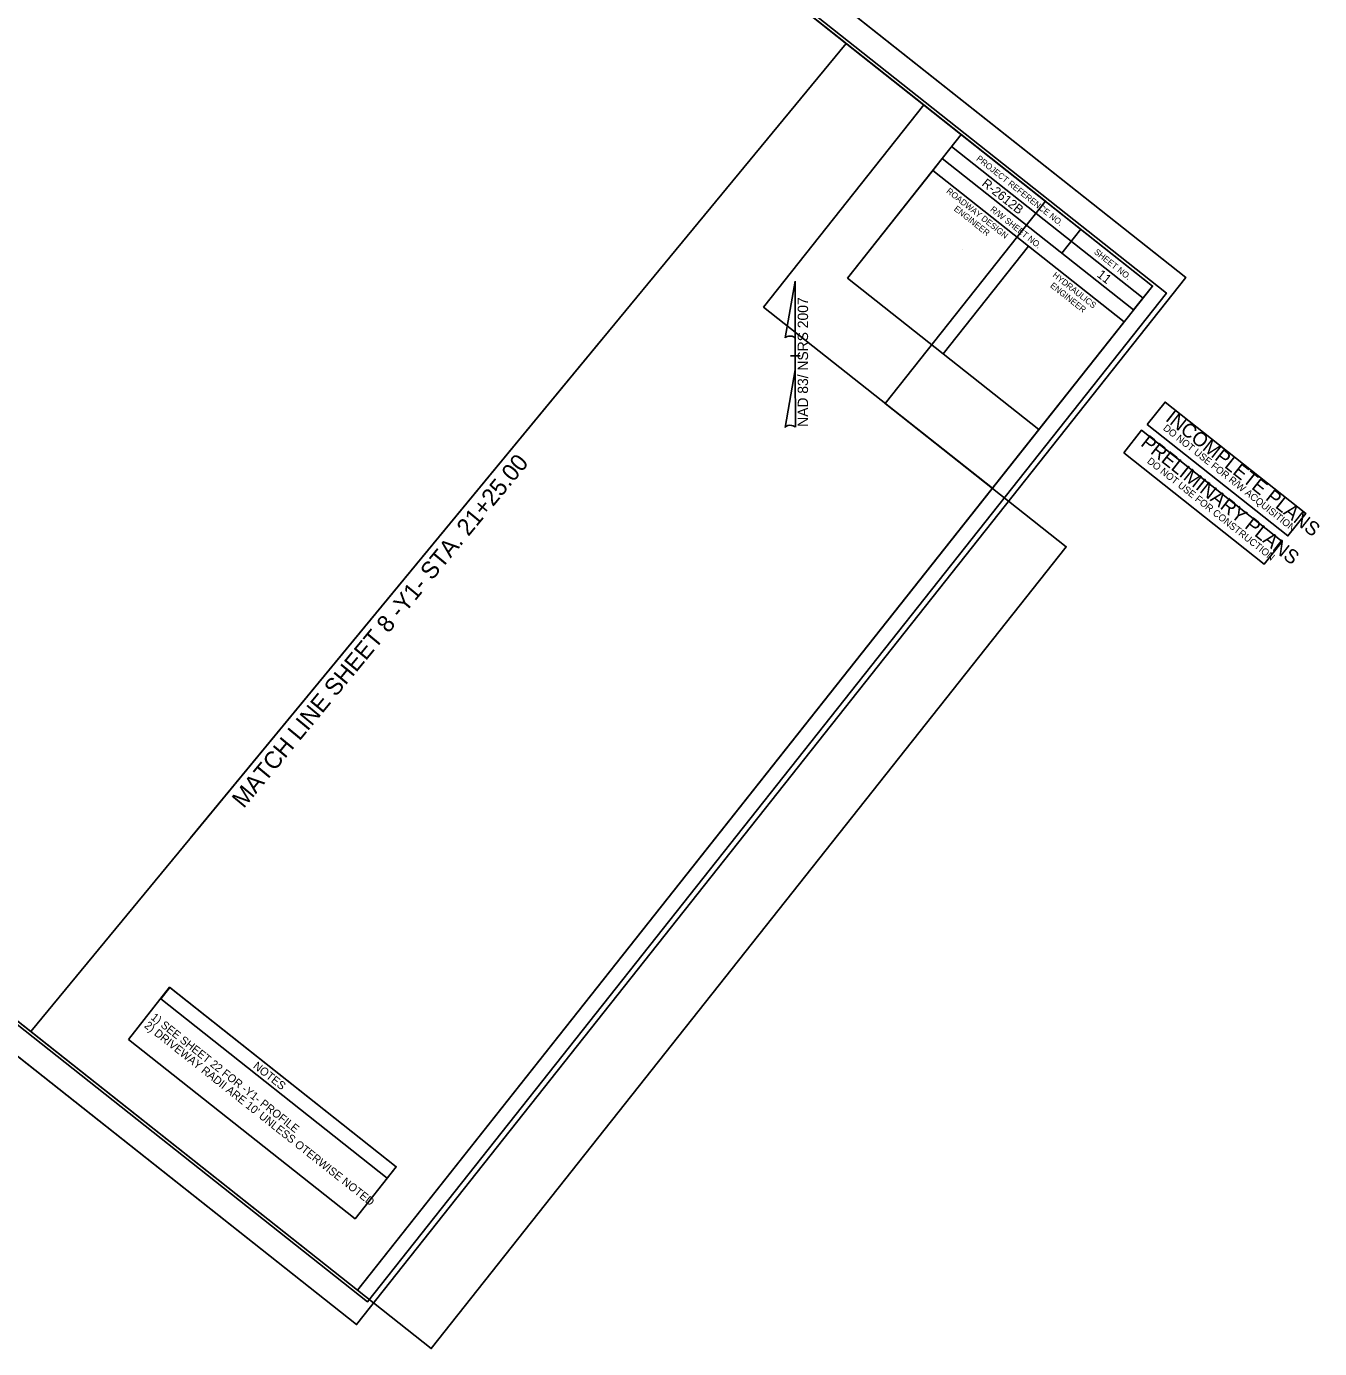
# Model space of a CAD drawing. Extents: x 1781036 to 1783156, y 813899 to 815868.
# Drawn here: x 1782096 to 1783156, y 813899 to 814983 of the extents above; entities that cross this region are included whole.
import ezdxf

# ---------------------------------------------------------------- set-up
doc = ezdxf.new("R2010")
doc.units = 0
for name, color, linetype in [('Matchline', 7, 'Continuous'), ('Matchline Text', 7, 'Continuous'), ('Prop DSN Text', 7, 'Continuous'), ('Prop Grid Mask', 7, 'Continuous'), ('Prop North Arrow NAD83 for Plan Sheets CELL', 7, 'Continuous'), ('Sheet Clip Boundary CELL', 7, 'Continuous'), ('Sheet Cutting Line CELL', 7, 'Continuous'), ('Sheet Data Field CELL', 7, 'Continuous'), ('Sheet Layout Plan Border', 7, 'Continuous'), ('Sheet North Arrow Point CELL', 7, 'Continuous'), ('Sheet Plan CELL', 7, 'Continuous'), ('Sheet Plan Layout CELL', 7, 'Continuous'), ('Sheet Plot Border Inside CELL', 7, 'Continuous'), ('Sheet Plot Border Outside CELL', 7, 'Continuous'), ('Sheet Sticker Incomplete CELL', 7, 'Continuous'), ('Sheet Sticker Preliminary CELL', 7, 'Continuous')]:
    doc.layers.add(name, color=color, linetype=linetype)

msp = doc.modelspace()

# ---------------------------------------------------------------- linework, layer by layer
at = {"layer": 'Matchline'}
msp.add_line((1782230.5, 814317.5), (1782567.5, 814726), dxfattribs=at)
at = {"layer": 'Prop Grid Mask'}
for points in [[(1782179.5, 814152.3), (1782365.3, 814005.2), (1782399.1, 814047.8), (1782213.3, 814195)], [(1782206.1, 814185.4), (1782391.7, 814038.5), (1782399.1, 814047.8), (1782213.5, 814194.8)]]:
    msp.add_lwpolyline(points, close=True, dxfattribs=at)
at = {"layer": 'Prop North Arrow NAD83 for Plan Sheets CELL'}
for p, q in [((1782717.9, 814727.4), (1782726.1, 814773.8)), ((1782726.1, 814773.8), (1782726.1, 814773.8)), ((1782726.1, 814773.8), (1782726.1, 814773.8)), ((1782726.1, 814773.8), (1782726.1, 814726)), ((1782726.1, 814701.2), (1782726.1, 814727.4)), ((1782726.1, 814726), (1782726.1, 814727.3)), ((1782725.7, 814712.8), (1782722.1, 814712.8)), ((1782722.1, 814712.8), (1782722.1, 814712.8)), ((1782722.2, 814712.8), (1782730.2, 814712.8)), ((1782726.1, 814701.2), (1782717.8, 814653.9)), ((1782726.2, 814654.1), (1782726.1, 814701.2))]:
    msp.add_line(p, q, dxfattribs=at)
for centre, start_param, end_param in [((1782722, 814726.9), 0.216388, 2.908219), ((1782722, 814653.8), 0.201328, 3.141593)]:
    msp.add_ellipse(centre, major_axis=(4.23, -0.03), ratio=0.461098, start_param=start_param, end_param=end_param, dxfattribs=at)
at = {"layer": 'Sheet Clip Boundary CELL'}
msp.add_lwpolyline([(1781191.1, 814877.8), (1782099.5, 814158.7), (1782767.8, 814968.8), (1781842.9, 815701.1)], close=True, dxfattribs=at)
at = {"layer": 'Sheet Cutting Line CELL'}
for p, q in [((1783046.2, 814777), (1781726.3, 815822)), ((1781046.6, 814963.5), (1782366.5, 813918.5))]:
    msp.add_line(p, q, dxfattribs=at)
at = {"layer": 'Sheet Layout Plan Border'}
msp.add_lwpolyline([(1781330.1, 814767.8), (1782427.7, 813898.8), (1782948.2, 814556.2), (1782799.8, 814673.7), (1782931.1, 814839.5), (1781981.8, 815591.1)], close=True, dxfattribs=at)
at = {"layer": 'Sheet North Arrow Point CELL'}
msp.add_line((1782863.2, 814800.2), (1782863.2, 814800.2), dxfattribs=at)
at = {"layer": 'Sheet Plan CELL'}
for p, q in [((1782854.3, 814884.3), (1783011.2, 814760.1)), ((1782846.5, 814874.5), (1782838.8, 814864.7)), ((1782846.5, 814874.5), (1783003.4, 814750.3)), ((1782846.5, 814874.5), (1783003.4, 814750.3)), ((1782960.1, 814816.5), (1782944.6, 814796.9)), ((1782917.2, 814802.6), (1782847.4, 814714.4))]:
    msp.add_line(p, q, dxfattribs=at)
for points in [[(1783019, 814769.9), (1781842.9, 815701.1), (1781191.1, 814877.8), (1782367.2, 813946.7)], [(1781191.1, 814877.8), (1781842.9, 815701), (1782862.1, 814894.1), (1782769, 814776.5), (1782925.8, 814652.3), (1782367.2, 813946.7)], [(1782862.1, 814894.1), (1783019, 814769.9), (1783003.4, 814750.3), (1782846.5, 814874.5)], [(1782838.8, 814864.7), (1782917.2, 814802.6), (1782847.4, 814714.4), (1782769, 814776.5)], [(1782917.2, 814802.6), (1782995.6, 814740.5), (1782925.8, 814652.3), (1782847.4, 814714.4)]]:
    msp.add_lwpolyline(points, close=True, dxfattribs=at)
at = {"layer": 'Sheet Plan Layout CELL'}
for points in [[(1781842.9, 815701), (1781191.1, 814877.8), (1782367.2, 813946.7), (1782887.7, 814604.2), (1782700.1, 814752.7), (1782831.4, 814918.5)], [(1782700.1, 814752.7), (1782887.7, 814604.1), (1783019, 814769.9), (1782831.4, 814918.5)]]:
    msp.add_lwpolyline(points, close=True, dxfattribs=at)
at = {"layer": 'Sheet Plot Border Inside CELL'}
msp.add_lwpolyline([(1781069.2, 814971.1), (1782375.4, 813937), (1783030.3, 814764.1), (1781724.1, 815798.3)], close=True, dxfattribs=at)
at = {"layer": 'Sheet Plot Border Outside CELL'}
msp.add_lwpolyline([(1781046.6, 814963.5), (1782366.5, 813918.5), (1783046.2, 814777), (1781726.3, 815822)], close=True, dxfattribs=at)
at = {"layer": 'Sheet Sticker Incomplete CELL'}
msp.add_lwpolyline([(1783014.6, 814656.3), (1783029.2, 814674.8), (1783144.5, 814583.5), (1783129.9, 814565.1)], close=True, dxfattribs=at)
at = {"layer": 'Sheet Sticker Preliminary CELL'}
msp.add_lwpolyline([(1782995.3, 814633.3), (1783009.9, 814651.7), (1783125.1, 814560.5), (1783110.5, 814542)], close=True, dxfattribs=at)

# ---------------------------------------------------------------- texts
at = {"layer": 'Matchline Text'}
msp.add_text('MATCH LINE SHEET 8 -Y1- STA. 21+25.00', height=14, rotation=50.4514, dxfattribs=at).set_placement((1782274, 814341.1))
at = {"layer": 'Prop DSN Text'}
for s, height, p in [("2) DRIVEWAY RADII ARE 10' UNLESS OTERWISE NOTED", 6.56, (1782192, 814162.6)), ('1) SEE SHEET 22 FOR -Y1- PROFILE ', 6.56, (1782197.4, 814169.3)), ('NOTES', 6.64, (1782281.2, 814129.4))]:
    msp.add_text(s, height=height, rotation=321.6309, dxfattribs=at).set_placement(p)
at = {"layer": 'Prop North Arrow NAD83 for Plan Sheets CELL'}
msp.add_text('NAD 83/ NSRS 2007', height=8.5, rotation=90, dxfattribs=at).set_placement((1782736.6, 814654.5))
at = {"layer": 'Sheet Data Field CELL'}
for s, p in [('R-2612B  ', (1782878.4, 814852.8)), ('11', (1782972.8, 814778.1))]:
    msp.add_text(s, height=7.5, rotation=321.6309, dxfattribs=at).set_placement(p)
at = {"layer": 'Sheet Plan CELL'}
for s, p in [('PROJECT REFERENCE NO.', (1782874.1, 814873.5)), ('ROADWAY DESIGN', (1782849.5, 814846.9)), ('ENGINEER', (1782855.7, 814832.3)), ('R/W SHEET NO.', (1782885.5, 814831.9)), ('SHEET NO.', (1782970.6, 814797)), ('ENGINEER', (1782934.6, 814769.4)), ('HYDRAULICS', (1782936.6, 814778))]:
    msp.add_text(s, height=5, rotation=321.6309, dxfattribs=at).set_placement(p)
at = {"layer": 'Sheet Sticker Incomplete CELL'}
for s, height, p in [('INCOMPLETE PLANS', 11.52, (1783028.9, 814660)), ('DO NOT USE FOR R/W ACQUISITION', 5.76, (1783027.1, 814652.5))]:
    msp.add_text(s, height=height, rotation=321.6309, dxfattribs=at).set_placement(p)
at = {"layer": 'Sheet Sticker Preliminary CELL'}
for s, height, p in [('PRELIMINARY PLANS', 11.52, (1783008.5, 814639.6)), ('DO NOT USE FOR CONSTRUCTION', 5.76, (1783014, 814625.4))]:
    msp.add_text(s, height=height, rotation=321.6309, dxfattribs=at).set_placement(p)

doc.saveas('drawing.dxf')
